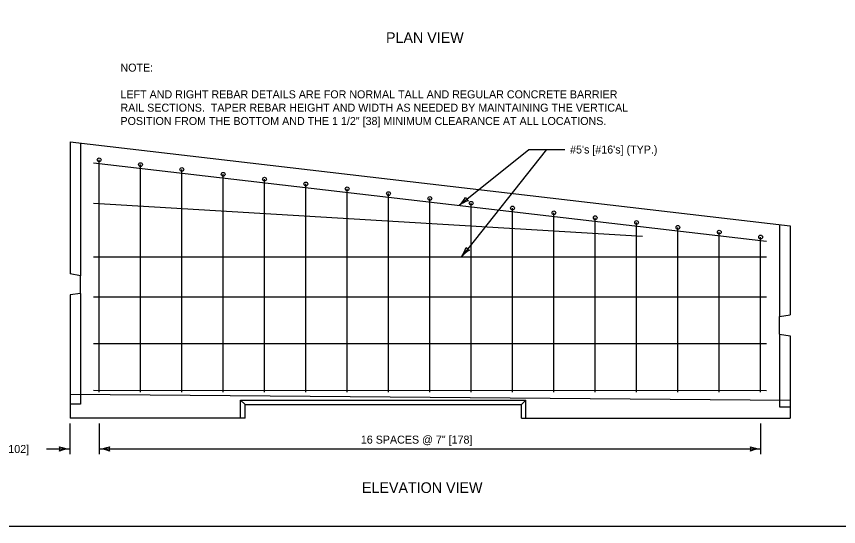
# Model space of a CAD drawing. Extents: x 49991.4 to 50021, y 49987.6 to 50011.4.
# Drawn here: x 50003.46 to 50009.63, y 49987.8 to 49991.62 of the extents above; entities that cross this region are included whole.
import ezdxf

# ---------------------------------------------------------------- set-up
doc = ezdxf.new("R2010")
doc.units = 0
for name, color, linetype in [('Level 1', 7, 'Continuous'), ('Level 2', 7, 'Continuous'), ('Level 3', 7, 'Continuous'), ('Level 4', 7, 'Continuous')]:
    doc.layers.add(name, color=color, linetype=linetype)

msp = doc.modelspace()

# ---------------------------------------------------------------- linework, layer by layer
at = {"layer": 'Level 1'}
for p, q in [((50003.8641, 49990.6821), (50009.2642, 49990.0523)), ((50003.8641, 49990.6821), (50003.8643, 49989.6922)), ((50004.0392, 49990.5259), (50009.0864, 49989.9372)), ((50004.0826, 49988.8071), (50004.0826, 49990.5474)), ((50004.3926, 49988.8071), (50004.3926, 49990.5115)), ((50004.7026, 49988.8071), (50004.7026, 49990.4753)), ((50005.0126, 49988.8071), (50005.0126, 49990.4391)), ((50005.3226, 49988.8071), (50005.3226, 49990.403)), ((50005.6326, 49988.8071), (50005.6326, 49990.3668)), ((50005.9426, 49988.8071), (50005.9426, 49990.3307)), ((50006.2527, 49988.8071), (50006.2527, 49990.2945)), ((50004.0392, 49990.2215), (50008.1571, 49989.9756)), ((50006.5627, 49988.8071), (50006.5627, 49990.2583)), ((50006.8727, 49988.8071), (50006.8727, 49990.2222)), ((50007.1827, 49988.8071), (50007.1827, 49990.186)), ((50007.4927, 49988.8071), (50007.4927, 49990.1499)), ((50007.8027, 49988.8071), (50007.8027, 49990.1137)), ((50008.1127, 49988.8071), (50008.1127, 49990.0776)), ((50008.4227, 49988.8071), (50008.4227, 49990.0414)), ((50009.2642, 49990.0523), (50009.2642, 49989.3868)), ((50008.7328, 49988.8071), (50008.7328, 49990.0052)), ((50009.0428, 49988.8071), (50009.0428, 49989.9689)), ((50004.0392, 49989.8211), (50009.0864, 49989.8211)), ((50003.9433, 49989.6769), (50003.8643, 49989.6922)), ((50003.9431, 49989.5466), (50003.9433, 49989.6769)), ((50003.9431, 49989.5466), (50003.8642, 49989.5347)), ((50003.8642, 49989.5347), (50003.8642, 49988.6121)), ((50004.0392, 49989.52), (50009.0864, 49989.52)), ((50009.1855, 49989.3744), (50009.2642, 49989.3868)), ((50009.1855, 49989.2405), (50009.1855, 49989.3744)), ((50009.1855, 49989.2405), (50009.2642, 49989.2281)), ((50009.2642, 49989.2281), (50009.2642, 49988.6121)), ((50004.0392, 49989.1697), (50009.0864, 49989.1697)), ((50004.0392, 49988.8215), (50009.0864, 49988.8196)), ((50005.1432, 49988.6121), (50005.1432, 49988.7467)), ((50005.1432, 49988.7467), (50005.1768, 49988.7129)), ((50005.1432, 49988.7467), (50007.2833, 49988.7467)), ((50007.2833, 49988.7467), (50007.2497, 49988.7129)), ((50007.2833, 49988.6121), (50007.2833, 49988.7467)), ((50005.1768, 49988.7129), (50007.2497, 49988.7129)), ((50005.1768, 49988.6121), (50005.1768, 49988.7129)), ((50007.2497, 49988.6121), (50007.2497, 49988.7129)), ((50005.1768, 49988.6121), (50003.8642, 49988.6121)), ((50007.2497, 49988.6121), (50009.2642, 49988.6121))]:
    msp.add_line(p, q, dxfattribs=at)
msp.add_lwpolyline([(49999.3835, 49998.9992), (50016.7501, 49998.9992), (50016.7501, 49987.7988), (49999.3835, 49987.7988)], close=True, dxfattribs=at)
for centre in [(50004.0826, 49990.5474), (50004.3926, 49990.5115), (50004.7026, 49990.4753), (50005.0126, 49990.4391), (50005.3226, 49990.403), (50005.6326, 49990.3668), (50005.9426, 49990.3307), (50006.2527, 49990.2945), (50006.5627, 49990.2583), (50006.8727, 49990.2222), (50007.1827, 49990.186), (50007.4927, 49990.1499), (50007.8027, 49990.1137), (50008.1127, 49990.0776), (50008.4227, 49990.0414), (50008.7328, 49990.0052), (50009.0428, 49989.9689)]:
    msp.add_circle(centre, 0.0142, dxfattribs=at)
at = {"layer": 'Level 3'}
for p, q in [((50006.7904, 49990.213), (50007.3052, 49990.6249)), ((50007.4367, 49990.6249), (50006.7996, 49989.8211)), ((50007.3052, 49990.6249), (50007.5743, 49990.6249)), ((50003.8621, 49988.5721), (50003.8621, 49988.3404)), ((50004.0835, 49988.5721), (50004.0835, 49988.3404)), ((50009.0428, 49988.5721), (50009.0428, 49988.3404)), ((50003.6886, 49988.3804), (50003.8621, 49988.3804)), ((50004.0835, 49988.3804), (50009.0428, 49988.3804))]:
    msp.add_line(p, q, dxfattribs=at)
for centre, radius, start, end in [((50006.6277, 49990.3805), 0.233, 311.49787, 330.74772), ((50006.8821, 49990.2861), 0.0548, 200.80938, 236.53174), ((50006.9137, 49990.0268), 0.2223, 106.12657, 126.31008), ((50006.6101, 49989.9567), 0.233, 324.42865, 343.6785), ((50006.8793, 49989.9216), 0.0548, 213.74016, 249.46252), ((50006.968, 49989.676), 0.2223, 119.05735, 139.24086), ((50003.8713, 49988.6025), 0.2223, 247.45601, 267.63952), ((50003.7339, 49988.3804), 0.0548, 342.13882, 17.86118), ((50003.8736, 49988.1477), 0.233, 92.82731, 112.07716), ((50004.072, 49988.6131), 0.233, 272.82731, 292.07716), ((50004.0744, 49988.1583), 0.2223, 67.45601, 87.63952), ((50004.2117, 49988.3804), 0.0548, 162.13882, 197.86118), ((50009.052, 49988.6025), 0.2223, 247.45601, 267.63952), ((50008.9146, 49988.3804), 0.0548, 342.13882, 17.86118), ((50009.0543, 49988.1477), 0.233, 92.82731, 112.07716)]:
    msp.add_arc(centre, radius, start, end, dxfattribs=at)
at = {"layer": 'Level 4'}
for p, q in [((50003.9433, 49990.6728), (50003.9433, 49989.6769)), ((50009.1855, 49990.0615), (50009.1855, 49989.3744)), ((50003.9431, 49989.5466), (50003.9431, 49988.7173)), ((50009.1855, 49989.2405), (50009.1855, 49988.6964)), ((50003.8642, 49988.7919), (50009.2642, 49988.7467)), ((50003.9431, 49988.7173), (50003.8642, 49988.7173)), ((50009.1855, 49988.6964), (50009.2642, 49988.6964))]:
    msp.add_line(p, q, dxfattribs=at)

# ---------------------------------------------------------------- texts
at = {"layer": 'Level 2'}
for s, height, p in [('PLAN VIEW', 0.08, (50006.2336, 49991.4236)), ('NOTE:', 0.06, (50004.2422, 49991.2086)), ('LEFT AND RIGHT REBAR DETAILS ARE FOR NORMAL TALL AND REGULAR CONCRETE BARRIER', 0.06, (50004.2422, 49991.0086)), ('RAIL SECTIONS.  TAPER REBAR HEIGHT AND WIDTH AS NEEDED BY MAINTAINING THE VERTICAL', 0.06, (50004.2422, 49990.9086)), ('POSITION FROM THE BOTTOM AND THE 1 1/2" [38] MINIMUM CLEARANCE AT ALL LOCATIONS.', 0.06, (50004.2422, 49990.8086)), ("#5's [#16's] (TYP.)", 0.06, (50007.6143, 49990.5949)), ('16 SPACES @ 7" [178]', 0.06, (50006.0448, 49988.4204)), ('4" [102]', 0.06, (50003.2837, 49988.3504)), ('ELEVATION VIEW', 0.08, (50006.0536, 49988.0504))]:
    msp.add_text(s, height=height, dxfattribs=at).set_placement(p)

doc.saveas('drawing.dxf')
